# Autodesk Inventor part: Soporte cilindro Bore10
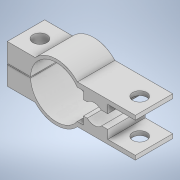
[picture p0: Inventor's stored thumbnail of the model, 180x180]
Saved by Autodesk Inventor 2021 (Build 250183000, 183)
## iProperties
Created: 2021-03
Part Number: Soporte cilindro Bore10
Material: Genérico
Document SubType Name: Modeling
Designer: ATOUZA
Density: 1 g/cm^3
Appearance: Valor por defecto
Author: ATOUZA
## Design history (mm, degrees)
sketch "Boceto1"
  geometry: L1 (-8, -4.75)-(-0.1, -4.75) reference; L2 (-8, -4.75)-(-12.563, -4.75) reference; L3 (-12.563, -4.75)-(-12.563, -5.65) reference; L4 (-12.563, -5.65)-(-0.1, -5.65) reference; L5 (-0.1, -5.65)-(-0.1, -4.75) reference; L6 (-0.1, 2.65)-(-12.563, 2.65) reference; L7 (-12.563, 2.65)-(-12.563, 1.75) reference; L8 (-12.563, 1.75)-(-8, 1.75) reference; L9 (-0.1, 1.75)-(-8, 1.75) reference; L10 (-0.1, 1.75)-(-0.1, 2.65) reference; L11 (-5.1, -6.65)-(-1.1, -6.65) reference; L12 (-9.15, -0.15)-(-8.65, -0.15) reference; L13 (-8.65, -2.85)-(-9.15, -2.85) reference; L14 (-7.472, -2.9)-(-6.3, -2.9) reference; L15 (-6.3, -2.9)-(-6.3, -0.1) reference; L16 (-6.3, -0.1)-(-7.472, -0.1) reference; L17 (-9.15, -0.15)-(-8.65, -0.15) reference; L18 (-7.577, 0)-(-6, 0) reference; L19 (-6, 0)-(-6, 1.275); L20 (-6, 1.275)-(-8.11, 1.275) reference; L21 (-8.91, 1.675)-(-11.2, 1.675) reference; L22 (-11.2, 1.675)-(-11.2, -4.675) reference; L23 (-6.3, -2.9)-(-6.3, -0.1) reference; L24 (-6.3, -0.1)-(-7.472, -0.1) reference; L25 (-7.404, 0)-(-6, 0); L26 (-6, -0.1)-(-7.31, -0.1); L27 (-5.1, -1.5)-(-12.389, -1.5); L28 (-11.2, 1.675)-(-11.2, 0.013); L29 (-11.2, 0.013)-(-10.383, 0.013); L30 (-6, -0.1)-(-6, 1.75); L31 (-11.2, 1.675)-(-12.509, 1.675); L32 (-12.482, 2.65)-(-0.1, 2.65); L33 (-0.1, 1.75)-(-6, 1.75); L34 (-0.1, 2.65)-(-0.1, 1.75); L35 (-0.1, -4.75)-(-6, -4.75); L36 (-0.1, -5.65)-(-0.1, -4.75); L37 (-12.482, -5.65)-(-0.1, -5.65); L38 (-6, -2.9)-(-6, -4.75); L39 (-6, -2.9)-(-7.31, -2.9); L40 (-11.2, -4.675)-(-11.2, -3.013); L41 (-11.2, -4.675)-(-12.509, -4.675); L42 (-10.383, -3.013)-(-11.2, -3.013); L43 (-16.987, 7.098)-(-16.987, -10.799); L44 (-21.41, -5.65)-(-33.873, -5.65); L45 (-21.491, -5.65)-(-27.491, -5.65); L46 (-33.873, 2.65)-(-21.41, 2.65); L47 (-21.491, 2.65)-(-27.491, 2.65); L48 (-33.873, 1.75)-(-33.873, 2.65); L49 (-33.873, -5.65)-(-33.873, -4.75); L50 (-26.396, 0)-(-27.973, 0); L51 (-26.57, 0)-(-27.973, 0); L52 (-33.873, -5.65)-(-33.873, -4.75); L53 (-27.491, 2.65)-(-27.491, -5.65); L54 (-17, -1.5)-(-33.873, -1.5); L55 (-17, -1.6)-(-33.873, -1.6); L56 (-17, -1.4)-(-33.873, -1.4); L57 (-22.499, -1.4)-(-27.491, -1.4); L58 (-22.499, -1.6)-(-27.491, -1.6); L59 (-27.491, 2.65)-(-27.491, -1.4); L60 (-27.491, -1.6)-(-27.491, -5.65); A1 r 5.5 centre (-17, -1.5) between (-12.563, 1.75) and (-12.563, -4.75) reference; A2 r 5.7 centre (-17, -1.5) between (-12.563, 2.078) and (-12.563, -5.078) reference; A3 r 1.35 centre (-8.65, -1.5) between (-8.65, -2.85) and (-8.65, -0.15) reference; A4 r 1.35 centre (-9.15, -1.5) between (-9.15, -0.15) and (-9.15, -2.85) reference; A5 r 2 centre (-8.9, -1.5) between (-7.472, -0.1) and (-7.472, -2.9) reference; A6 r 1.35 centre (-8.65, -1.5) between (-8.65, -2.85) and (-8.65, -0.15) reference; A7 r 1.35 centre (-9.15, -1.5) between (-9.15, -0.15) and (-9.15, -2.85) reference; A8 r 1 centre (-8.11, 2.275) between (-8.91, 1.675) and (-8.11, 1.275) reference; A9 r 2 centre (-8.9, -1.5) between (-7.472, -0.1) and (-7.577, 0) reference; A10 r 2.119 centre (-8.9, -1.5) between (-7.31, -0.1) and (-10.383, 0.013); A11 r 2.119 centre (-8.9, -1.5) between (-10.383, -3.013) and (-7.31, -2.9); A12 r 5.5 centre (-17, -1.5) between (-12.509, 1.675) and (-22.499, -1.4); A13 r 5.5 centre (-17, -1.5) between (-22.499, -1.6) and (-12.509, -4.675); A14 r 6.135 centre (-17, -1.5) between (-12.482, 2.65) and (-21.518, 2.65); A15 r 6.135 centre (-17, -1.5) between (-21.518, -5.65) and (-12.482, -5.65); 8 further points
  constraints: 74 end point, 21 symmetric about line, 14 point on line, 13 point on circle, 6 centre point, 4 horizontal, 4 perpendicular, 3 coincident, 3 parallel, 3 vertical, 2 collinear, 1 other
  dimensions: "d1" = 0.1 distance between parallel lines of L54 L55; "d2" = 0.1 distance between parallel lines of L54 L56; "d3" = 12.38226 distance of L37.start L4.end; "d4" = 6 distance of L45.start L45.end
extrude "Extrusión1" new body sketch "Boceto1" distance "d5" = 8; taper "d6" = 0 deg
sketch "Boceto2"
  geometry: L1 (0, 0)-(0, -8) reference; L2 (0, -4)-(5.973, -4); L3 (5.973, 0)-(5.973, -8) reference; L4 (15.009, 0)-(15.009, -8) reference; L5 (2.987, -8)-(2.987, 0); L6 (5.973, 0)-(0, 0) reference; L7 (21.491, 0)-(21.491, -8) reference; L8 (21.491, 0)-(21.491, -8) reference; L9 (21.491, -4)-(27.25, -4); L10 (24.37, -8)-(24.37, 0); 4 further points
  constraints: 8 end point, 6 midpoint, 1 point on line, 1 vertical
hole "Agujero1" sketch "Boceto2" at (2.987, -4), (24.352, -4.021) diameter "d7" = 3; stored, may be unused: countersink angle "d11" = 90 deg, drill point angle "d13" = 118 deg; dims "d8" = 6, "d9" = 3, "d10" = 2, "d12" = 8
node "Sólido1"
node "Referencia1"
node "Referencia2"
node "Referencia3"
node "Referencia4"
node "Referencia5"
node "Referencia6"
other parameters: "d0" = 4.2
